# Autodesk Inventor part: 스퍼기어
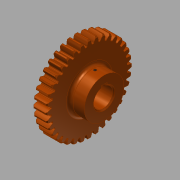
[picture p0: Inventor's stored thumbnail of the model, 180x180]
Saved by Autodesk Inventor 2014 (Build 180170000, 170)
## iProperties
Created: 2019-01
Part Number: 스퍼기어
Material: 알루미늄 6061
Document SubType Name: Modeling
Designer: mduedu
Density: 1 g/cm^3
Appearance: Smooth - Light Orange
Author: mduedu
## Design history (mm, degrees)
sketch "스케치1"
  geometry: C1 r 33.5 at (0, 0); 1 further point
  constraints: 1 centre point, 1 coincident
  dimensions: "d0" = 67 diameter of C1
extrude "돌출1" new body sketch "스케치1" stored distance "d2" = 12; taper "d3" = 0 deg
sketch "스케치2" dims "d4" = 72
  geometry: L1 (0, 0)-(-38, 0); L2 (0, 0)-(0, 38); L3 (-0.57, 0)-(-0.57, 37.996); L4 (-1.57, 0)-(-1.57, 37.968); L5 (-2.07, 0)-(-2.07, 37.944); C1 r 33.5 at (0, 0); A1 r 38 centre (0, 0) between (-38, 0) and (0, 38); A2 r 9.246 centre (7.162, 32.926) between (-0.57, 37.996) and (-2.07, 33.436); A3 r 9.246 centre (-7.162, 32.926) between (2.07, 33.436) and (0.57, 37.996); A4 r 33.5 centre (0, 0) between (2.07, 33.436) and (-2.07, 33.436); A5 r 38 centre (0, 0) between (0.57, 37.996) and (-0.57, 37.996); 3 further points
  constraints: 14 point on circle, 10 end point, 6 centre point, 5 coincident, 5 point on line, 3 symmetric about line, 2 parallel, 2 perpendicular, 1 horizontal, 7 other
  dimensions: "d6" = 76 diameter of A1; "d7" = 0.5 distance between parallel lines of L4 L5; "d8" = 1 distance between parallel lines of L3 L4; "d9" = 1.57 distance between parallel lines of L2 L4
extrude "돌출2" join sketch "스케치2" stored distance "d10" = 0; taper "d11" = 0 deg
chamfer "모따기1" distance "d12" = 1; stored, may be unused: second distance "d13" = 2, angle "d14" = 45 deg
fillet "모깎기1" dims "d15" = 0.5
sketch "스케치3"
  geometry: C1 r 17.5 at (0, 0); 1 further point
  constraints: 1 centre point, 1 coincident
  dimensions: "d19" = 35 diameter of C1
extrude "돌출3" join sketch "스케치3" distance "d20" = 13; taper "d21" = 0 deg
sketch "스케치4"
  geometry: L1 (-2.5, 8.124)-(2.5, 8.124); L2 (2.5, 8.124)-(2.5, 10.8); L3 (2.5, 10.8)-(-2.5, 10.8); L4 (-2.5, 10.8)-(-2.5, 8.124); A1 r 8.5 centre (0, 0) between (-2.5, 8.124) and (2.5, 8.124); 1 further point
  constraints: 8 end point, 2 parallel, 2 point on circle, 1 centre point, 1 coincident, 1 horizontal, 1 perpendicular
  dimensions: "d22" = 17 diameter of A1; "d23" = 5 distance of L2.end L3.end; "d24" = 19.3 dimension on A1 L3
extrude "돌출4" cut sketch "스케치4" stored distance "d25" = 13; taper "d26" = 0 deg
sketch "스케치5"
  geometry: C1 r 15 at (0, 0); C2 r 27.5 at (0, 0); 1 further point
  constraints: 2 centre point, 2 coincident
  dimensions: "d33" = 30 diameter of C1; "d34" = 55 diameter of C2
extrude "돌출5" cut sketch "스케치5" distance "d30" = 6; taper "d31" = 0 deg
fillet "모깎기2" dims "d32" = 3
node "작업 평면1"
sketch "스케치6"
  geometry: L1 (17.5, 13)-(-17.5, 13) reference; 2 further points
  constraints: 1 vertical alignment
  dimensions: "d35" = 8 distance from line of point (0, 5) L1
hole "구멍1" sketch "스케치6" at (0, 5) diameter "d36" = 2.459; stored, may be unused: countersink angle "d40" = 90 deg, drill point angle "d42" = 118 deg; dims "d37" = 6, "d38" = 4, "d39" = 2, "d41" = 8
fillet "모깎기3" dims "d43" = 3
chamfer "모따기2" distance "d44" = 1; stored, may be unused: second distance "d45" = 2, angle "d46" = 45 deg
node "솔리드1"
pattern_circular "원형 패턴1" dims "d17" = 360 deg
